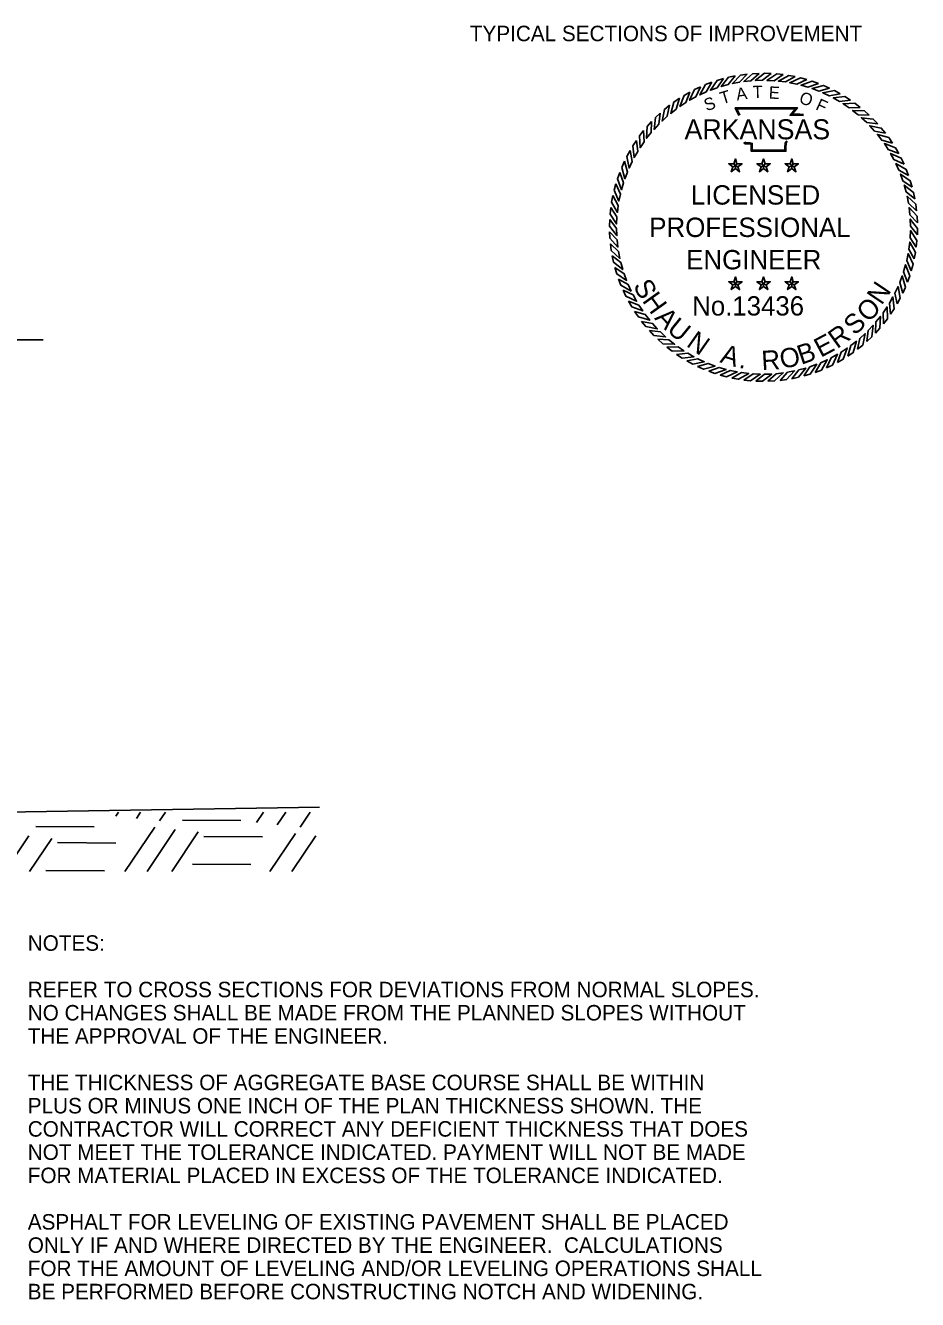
# Model space of a CAD drawing. Extents: x 1001270 to 1003428, y 1840152 to 1842912.
# Drawn here: x 1001393.92 to 1001428.48, y 1842430.26 to 1842479.61 of the extents above; entities that cross this region are included whole.
import ezdxf

# ---------------------------------------------------------------- set-up
doc = ezdxf.new("R2010")
doc.units = 0
for name, color, linetype in [('1', 7, 'Continuous'), ('19', 7, 'Continuous'), ('G-ANNO-SYMB', 7, 'Continuous')]:
    doc.layers.add(name, color=color, linetype=linetype)

msp = doc.modelspace()

# ---------------------------------------------------------------- linework, layer by layer
at = {"layer": '19'}
for p, q in [((1001374.315, 1842467.431), (1001394.601, 1842467.431)), ((1001393.111, 1842449.131), (1001405.316, 1842449.334)), ((1001397.423, 1842448.982), (1001397.529, 1842449.132)), ((1001398.217, 1842448.89), (1001398.383, 1842449.134)), ((1001399.113, 1842448.798), (1001399.339, 1842449.137)), ((1001402.877, 1842448.742), (1001403.139, 1842449.138)), ((1001403.672, 1842448.651), (1001404.003, 1842449.139)), ((1001404.567, 1842448.558), (1001404.948, 1842449.132)), ((1001394.326, 1842448.587), (1001396.586, 1842448.566)), ((1001397.775, 1842446.835), (1001398.927, 1842448.556)), ((1001400, 1842448.827), (1001402.261, 1842448.816)), ((1001393.12, 1842446.831), (1001394.046, 1842448.214)), ((1001394.075, 1842446.833), (1001394.942, 1842448.122)), ((1001398.629, 1842446.837), (1001399.722, 1842448.464)), ((1001399.585, 1842446.839), (1001400.617, 1842448.372)), ((1001400.83, 1842448.199), (1001403.101, 1842448.187)), ((1001403.385, 1842446.84), (1001404.381, 1842448.316)), ((1001404.24, 1842446.843), (1001405.176, 1842448.224)), ((1001395.166, 1842447.958), (1001397.426, 1842447.936)), ((1001400.389, 1842447.129), (1001402.648, 1842447.107)), ((1001394.713, 1842446.878), (1001396.984, 1842446.866))]:
    msp.add_line(p, q, dxfattribs=at)
at = {"layer": 'G-ANNO-SYMB'}
for points in [[(1001421.88, 1842477.723), (1001421.625, 1842477.69), (1001421.314, 1842477.356), (1001421.586, 1842477.408)], [(1001422.347, 1842477.755), (1001422.091, 1842477.742), (1001421.754, 1842477.433), (1001422.029, 1842477.464)], [(1001422.816, 1842477.75), (1001422.559, 1842477.757), (1001422.199, 1842477.476), (1001422.476, 1842477.485)], [(1001423.282, 1842477.708), (1001423.027, 1842477.736), (1001422.646, 1842477.483), (1001422.923, 1842477.47)], [(1001423.744, 1842477.63), (1001423.492, 1842477.677), (1001423.092, 1842477.456), (1001423.367, 1842477.421)], [(1001420.078, 1842477.236), (1001419.846, 1842477.126), (1001419.653, 1842476.711), (1001419.896, 1842476.845)], [(1001420.513, 1842477.41), (1001420.273, 1842477.319), (1001420.048, 1842476.921), (1001420.3, 1842477.035)], [(1001420.96, 1842477.55), (1001420.714, 1842477.478), (1001420.458, 1842477.099), (1001420.719, 1842477.193)], [(1001421.416, 1842477.655), (1001421.165, 1842477.602), (1001420.881, 1842477.244), (1001421.148, 1842477.317)], [(1001424.198, 1842477.516), (1001423.951, 1842477.583), (1001423.535, 1842477.393), (1001423.806, 1842477.337)], [(1001424.642, 1842477.366), (1001424.401, 1842477.452), (1001423.971, 1842477.296), (1001424.237, 1842477.219)], [(1001425.073, 1842477.182), (1001424.839, 1842477.287), (1001424.398, 1842477.165), (1001424.658, 1842477.067)], [(1001419.256, 1842476.787), (1001419.045, 1842476.642), (1001418.919, 1842476.203), (1001419.138, 1842476.373)], [(1001419.658, 1842477.028), (1001419.436, 1842476.9), (1001419.276, 1842476.471), (1001419.507, 1842476.624)], [(1001425.488, 1842476.965), (1001425.263, 1842477.088), (1001424.814, 1842477.001), (1001425.065, 1842476.883)], [(1001425.885, 1842476.716), (1001425.67, 1842476.856), (1001425.216, 1842476.805), (1001425.457, 1842476.667)], [(1001418.515, 1842476.215), (1001418.329, 1842476.039), (1001418.273, 1842475.585), (1001418.462, 1842475.787)], [(1001418.874, 1842476.516), (1001418.675, 1842476.355), (1001418.584, 1842475.907), (1001418.789, 1842476.093)], [(1001426.261, 1842476.437), (1001426.058, 1842476.594), (1001425.601, 1842476.578), (1001425.83, 1842476.422)], [(1001426.614, 1842476.129), (1001426.424, 1842476.301), (1001425.967, 1842476.321), (1001426.183, 1842476.148)], [(1001418.18, 1842475.888), (1001418.008, 1842475.697), (1001417.988, 1842475.241), (1001418.161, 1842475.457)], [(1001426.942, 1842475.794), (1001426.765, 1842475.981), (1001426.312, 1842476.036), (1001426.514, 1842475.847)], [(1001427.242, 1842475.435), (1001427.081, 1842475.634), (1001426.633, 1842475.726), (1001426.82, 1842475.521)], [(1001417.872, 1842475.535), (1001417.716, 1842475.332), (1001417.732, 1842474.875), (1001417.887, 1842475.104)], [(1001427.513, 1842475.053), (1001427.368, 1842475.265), (1001426.929, 1842475.391), (1001427.099, 1842475.172)], [(1001417.344, 1842474.762), (1001417.221, 1842474.537), (1001417.308, 1842474.088), (1001417.426, 1842474.339)], [(1001417.593, 1842475.159), (1001417.453, 1842474.944), (1001417.504, 1842474.49), (1001417.642, 1842474.73)], [(1001427.754, 1842474.651), (1001427.626, 1842474.873), (1001427.198, 1842475.033), (1001427.35, 1842474.802)], [(1001417.127, 1842474.347), (1001417.022, 1842474.113), (1001417.144, 1842473.672), (1001417.242, 1842473.931)], [(1001421.427, 1842474.167), (1001421.366, 1842474.251), (1001421.167, 1842474.251), (1001421.328, 1842474.135)], [(1001421.427, 1842474.167), (1001421.488, 1842474.251), (1001421.427, 1842474.44), (1001421.366, 1842474.251)], [(1001421.427, 1842474.167), (1001421.526, 1842474.135), (1001421.686, 1842474.251), (1001421.488, 1842474.251)], [(1001422.518, 1842474.167), (1001422.456, 1842474.251), (1001422.258, 1842474.251), (1001422.419, 1842474.135)], [(1001422.518, 1842474.167), (1001422.579, 1842474.251), (1001422.518, 1842474.44), (1001422.456, 1842474.251)], [(1001422.518, 1842474.167), (1001422.617, 1842474.135), (1001422.777, 1842474.251), (1001422.579, 1842474.251)], [(1001423.609, 1842474.167), (1001423.547, 1842474.251), (1001423.349, 1842474.251), (1001423.51, 1842474.135)], [(1001423.609, 1842474.167), (1001423.67, 1842474.251), (1001423.609, 1842474.44), (1001423.547, 1842474.251)], [(1001423.609, 1842474.167), (1001423.708, 1842474.135), (1001423.868, 1842474.251), (1001423.67, 1842474.251)], [(1001427.962, 1842474.231), (1001427.852, 1842474.463), (1001427.438, 1842474.656), (1001427.571, 1842474.413)], [(1001428.137, 1842473.796), (1001428.045, 1842474.036), (1001427.647, 1842474.261), (1001427.761, 1842474.009)], [(1001416.943, 1842473.916), (1001416.857, 1842473.674), (1001417.013, 1842473.245), (1001417.09, 1842473.511)], [(1001421.427, 1842474.167), (1001421.328, 1842474.135), (1001421.266, 1842473.946), (1001421.427, 1842474.063)], [(1001421.427, 1842474.167), (1001421.427, 1842474.063), (1001421.587, 1842473.946), (1001421.526, 1842474.135)], [(1001422.518, 1842474.167), (1001422.419, 1842474.135), (1001422.357, 1842473.946), (1001422.518, 1842474.063)], [(1001422.518, 1842474.167), (1001422.518, 1842474.063), (1001422.678, 1842473.946), (1001422.617, 1842474.135)], [(1001423.609, 1842474.167), (1001423.51, 1842474.135), (1001423.448, 1842473.946), (1001423.609, 1842474.063)], [(1001423.609, 1842474.167), (1001423.609, 1842474.063), (1001423.769, 1842473.946), (1001423.708, 1842474.135)], [(1001428.277, 1842473.349), (1001428.204, 1842473.596), (1001427.825, 1842473.851), (1001427.919, 1842473.591)], [(1001416.793, 1842473.472), (1001416.726, 1842473.224), (1001416.916, 1842472.808), (1001416.972, 1842473.08)], [(1001428.381, 1842472.893), (1001428.328, 1842473.144), (1001427.97, 1842473.428), (1001428.044, 1842473.161)], [(1001416.679, 1842473.018), (1001416.632, 1842472.766), (1001416.854, 1842472.366), (1001416.888, 1842472.641)], [(1001428.449, 1842472.429), (1001428.417, 1842472.684), (1001428.082, 1842472.996), (1001428.134, 1842472.723)], [(1001416.601, 1842472.556), (1001416.574, 1842472.301), (1001416.826, 1842471.92), (1001416.839, 1842472.196)], [(1001428.481, 1842471.962), (1001428.468, 1842472.218), (1001428.159, 1842472.555), (1001428.19, 1842472.28)], [(1001416.559, 1842472.089), (1001416.552, 1842471.833), (1001416.833, 1842471.473), (1001416.825, 1842471.75)], [(1001428.476, 1842471.494), (1001428.483, 1842471.75), (1001428.202, 1842472.11), (1001428.211, 1842471.833)], [(1001416.554, 1842471.621), (1001416.567, 1842471.365), (1001416.876, 1842471.028), (1001416.845, 1842471.303)], [(1001428.434, 1842471.027), (1001428.462, 1842471.282), (1001428.209, 1842471.663), (1001428.196, 1842471.387)], [(1001416.586, 1842471.154), (1001416.619, 1842470.899), (1001416.953, 1842470.587), (1001416.901, 1842470.86)], [(1001428.242, 1842470.111), (1001428.309, 1842470.358), (1001428.119, 1842470.775), (1001428.063, 1842470.503)], [(1001428.356, 1842470.565), (1001428.404, 1842470.817), (1001428.182, 1842471.217), (1001428.147, 1842470.942)], [(1001416.654, 1842470.69), (1001416.707, 1842470.439), (1001417.065, 1842470.154), (1001416.992, 1842470.422)], [(1001428.092, 1842469.667), (1001428.179, 1842469.909), (1001428.022, 1842470.338), (1001427.945, 1842470.072)], [(1001416.759, 1842470.234), (1001416.831, 1842469.987), (1001417.21, 1842469.732), (1001417.116, 1842469.992)], [(1001416.899, 1842469.786), (1001416.99, 1842469.547), (1001417.388, 1842469.322), (1001417.274, 1842469.574)], [(1001421.427, 1842469.599), (1001421.488, 1842469.683), (1001421.427, 1842469.872), (1001421.366, 1842469.683)], [(1001422.518, 1842469.599), (1001422.579, 1842469.683), (1001422.518, 1842469.872), (1001422.456, 1842469.683)], [(1001423.609, 1842469.599), (1001423.67, 1842469.683), (1001423.609, 1842469.872), (1001423.547, 1842469.683)], [(1001427.909, 1842469.236), (1001428.013, 1842469.47), (1001427.891, 1842469.911), (1001427.793, 1842469.651)], [(1001417.073, 1842469.352), (1001417.183, 1842469.12), (1001417.598, 1842468.927), (1001417.464, 1842469.17)], [(1001421.427, 1842469.599), (1001421.366, 1842469.683), (1001421.167, 1842469.683), (1001421.328, 1842469.567)], [(1001421.427, 1842469.599), (1001421.328, 1842469.567), (1001421.266, 1842469.378), (1001421.427, 1842469.495)], [(1001421.427, 1842469.599), (1001421.526, 1842469.567), (1001421.686, 1842469.683), (1001421.488, 1842469.683)], [(1001421.427, 1842469.599), (1001421.427, 1842469.495), (1001421.587, 1842469.378), (1001421.526, 1842469.567)], [(1001422.518, 1842469.599), (1001422.456, 1842469.683), (1001422.258, 1842469.683), (1001422.419, 1842469.567)], [(1001422.518, 1842469.599), (1001422.419, 1842469.567), (1001422.357, 1842469.378), (1001422.518, 1842469.495)], [(1001422.518, 1842469.599), (1001422.617, 1842469.567), (1001422.777, 1842469.683), (1001422.579, 1842469.683)], [(1001422.518, 1842469.599), (1001422.518, 1842469.495), (1001422.678, 1842469.378), (1001422.617, 1842469.567)], [(1001423.609, 1842469.599), (1001423.547, 1842469.683), (1001423.349, 1842469.683), (1001423.51, 1842469.567)], [(1001423.609, 1842469.599), (1001423.51, 1842469.567), (1001423.448, 1842469.378), (1001423.609, 1842469.495)], [(1001423.609, 1842469.599), (1001423.708, 1842469.567), (1001423.868, 1842469.683), (1001423.67, 1842469.683)], [(1001423.609, 1842469.599), (1001423.609, 1842469.495), (1001423.769, 1842469.378), (1001423.708, 1842469.567)], [(1001427.691, 1842468.821), (1001427.814, 1842469.046), (1001427.727, 1842469.495), (1001427.609, 1842469.244)], [(1001417.282, 1842468.932), (1001417.409, 1842468.71), (1001417.838, 1842468.55), (1001417.685, 1842468.781)], [(1001427.442, 1842468.424), (1001427.583, 1842468.639), (1001427.531, 1842469.093), (1001427.394, 1842468.853)], [(1001417.522, 1842468.53), (1001417.667, 1842468.318), (1001418.106, 1842468.192), (1001417.936, 1842468.411)], [(1001426.855, 1842467.695), (1001427.027, 1842467.885), (1001427.047, 1842468.342), (1001426.874, 1842468.126)], [(1001427.163, 1842468.048), (1001427.32, 1842468.251), (1001427.304, 1842468.708), (1001427.148, 1842468.479)], [(1001417.793, 1842468.148), (1001417.954, 1842467.949), (1001418.402, 1842467.857), (1001418.216, 1842468.062)], [(1001426.52, 1842467.368), (1001426.707, 1842467.544), (1001426.763, 1842467.998), (1001426.573, 1842467.795)], [(1001418.094, 1842467.789), (1001418.27, 1842467.602), (1001418.724, 1842467.547), (1001418.522, 1842467.736)], [(1001418.421, 1842467.454), (1001418.612, 1842467.282), (1001419.069, 1842467.262), (1001418.852, 1842467.435)], [(1001425.779, 1842466.796), (1001425.991, 1842466.941), (1001426.117, 1842467.38), (1001425.898, 1842467.21)], [(1001426.161, 1842467.067), (1001426.361, 1842467.228), (1001426.452, 1842467.676), (1001426.247, 1842467.49)], [(1001418.774, 1842467.146), (1001418.978, 1842466.989), (1001419.435, 1842467.005), (1001419.205, 1842467.161)], [(1001419.15, 1842466.867), (1001419.365, 1842466.726), (1001419.82, 1842466.778), (1001419.579, 1842466.915)], [(1001424.957, 1842466.347), (1001425.189, 1842466.457), (1001425.382, 1842466.872), (1001425.14, 1842466.738)], [(1001425.377, 1842466.555), (1001425.599, 1842466.683), (1001425.76, 1842467.111), (1001425.528, 1842466.959)], [(1001419.547, 1842466.618), (1001419.772, 1842466.495), (1001420.221, 1842466.582), (1001419.97, 1842466.7)], [(1001419.962, 1842466.401), (1001420.196, 1842466.296), (1001420.637, 1842466.418), (1001420.378, 1842466.516)], [(1001420.393, 1842466.217), (1001420.635, 1842466.13), (1001421.064, 1842466.287), (1001420.798, 1842466.364)], [(1001423.619, 1842465.928), (1001423.87, 1842465.981), (1001424.155, 1842466.339), (1001423.887, 1842466.265)], [(1001424.076, 1842466.033), (1001424.322, 1842466.105), (1001424.577, 1842466.484), (1001424.317, 1842466.39)], [(1001424.523, 1842466.173), (1001424.762, 1842466.264), (1001424.988, 1842466.662), (1001424.735, 1842466.548)], [(1001420.837, 1842466.067), (1001421.085, 1842466), (1001421.501, 1842466.19), (1001421.229, 1842466.246)], [(1001421.291, 1842465.953), (1001421.543, 1842465.906), (1001421.943, 1842466.127), (1001421.668, 1842466.162)], [(1001421.753, 1842465.875), (1001422.008, 1842465.847), (1001422.39, 1842466.1), (1001422.113, 1842466.113)], [(1001422.22, 1842465.833), (1001422.476, 1842465.826), (1001422.837, 1842466.107), (1001422.56, 1842466.098)], [(1001422.688, 1842465.828), (1001422.944, 1842465.841), (1001423.282, 1842466.15), (1001423.006, 1842466.119)], [(1001423.156, 1842465.86), (1001423.41, 1842465.893), (1001423.722, 1842466.227), (1001423.45, 1842466.175)]]:
    msp.add_lwpolyline(points, close=True, dxfattribs=at)
for points in [[(1001421.562, 1842476.121), (1001421.423, 1842476.423), (1001423.829, 1842476.424), (1001423.628, 1842476.171), (1001423.792, 1842476.174), (1001423.928, 1842476.175), (1001424.065, 1842476.16)], [(1001421.596, 1842476.137), (1001421.482, 1842476.385), (1001423.75, 1842476.386), (1001423.548, 1842476.132), (1001423.792, 1842476.135), (1001423.926, 1842476.137), (1001424.06, 1842476.123)], [(1001423.45, 1842475.113), (1001423.409, 1842475.08), (1001423.395, 1842475.03), (1001423.382, 1842474.905), (1001423.382, 1842474.739), (1001422.038, 1842474.739), (1001422.038, 1842474.963), (1001422.038, 1842475.013), (1001421.984, 1842475.03), (1001421.793, 1842475.03), (1001421.759, 1842475.082)], [(1001423.426, 1842475.143), (1001423.375, 1842475.101), (1001423.358, 1842475.037), (1001423.344, 1842474.907), (1001423.344, 1842474.777), (1001422.077, 1842474.777), (1001422.077, 1842474.963), (1001422.077, 1842475.041), (1001421.99, 1842475.068), (1001421.813, 1842475.068), (1001421.791, 1842475.102)]]:
    msp.add_lwpolyline(points, dxfattribs=at)

# ---------------------------------------------------------------- texts
at = {"layer": '1'}
msp.add_text('TYPICAL SECTIONS OF IMPROVEMENT', height=0.6, dxfattribs=at).set_placement((1001411.138, 1842479))
at = {"layer": '19'}
for s, p in [('NOTES:', (1001394.009, 1842443.768)), ('REFER TO CROSS SECTIONS FOR DEVIATIONS FROM NORMAL SLOPES.', (1001394.009, 1842441.968)), ('NO CHANGES SHALL BE MADE FROM THE PLANNED SLOPES WITHOUT', (1001394.009, 1842441.068)), ('THE APPROVAL OF THE ENGINEER.', (1001394.009, 1842440.168)), ('THE THICKNESS OF AGGREGATE BASE COURSE SHALL BE WITHIN', (1001394.009, 1842438.368)), ('PLUS OR MINUS ONE INCH OF THE PLAN THICKNESS SHOWN. THE', (1001394.009, 1842437.468)), ('CONTRACTOR WILL CORRECT ANY DEFICIENT THICKNESS THAT DOES', (1001394.009, 1842436.568)), ('NOT MEET THE TOLERANCE INDICATED. PAYMENT WILL NOT BE MADE', (1001394.009, 1842435.668)), ('FOR MATERIAL PLACED IN EXCESS OF THE TOLERANCE INDICATED.', (1001394.009, 1842434.768)), ('ASPHALT FOR LEVELING OF EXISTING PAVEMENT SHALL BE PLACED', (1001394.009, 1842432.968)), ('ONLY IF AND WHERE DIRECTED BY THE ENGINEER.  CALCULATIONS', (1001394.009, 1842432.068)), ('FOR THE AMOUNT OF LEVELING AND/OR LEVELING OPERATIONS SHALL', (1001394.009, 1842431.168)), ('BE PERFORMED BEFORE CONSTRUCTING NOTCH AND WIDENING.', (1001394.009, 1842430.268))]:
    msp.add_text(s, height=0.6, dxfattribs=at).set_placement(p)
at = {"layer": 'G-ANNO-SYMB'}
for s, height, rotation, p in [('A', 0.475, 8.6788, (1001421.489, 1842476.701)), ('T', 0.475, 1.4789, (1001422.102, 1842476.795)), ('E', 0.475, 356.672, (1001422.709, 1842476.781)), ('S', 0.475, 19.7726, (1001420.309, 1842476.279)), ('T', 0.475, 16.9015, (1001420.912, 1842476.55)), ('O', 0.475, 341.2218, (1001423.862, 1842476.618)), ('F', 0.475, 335.3628, (1001424.501, 1842476.368)), ('ARKANSAS', 0.7747, 360, (1001419.456, 1842475.2)), ('LICENSED', 0.75, 360, (1001419.696, 1842472.671)), ('PROFESSIONAL', 0.75, 360, (1001418.089, 1842471.416)), ('ENGINEER', 0.75, 360, (1001419.518, 1842470.162)), ('S', 0.75, 298.1636, (1001417.45, 1842469.532)), ('H', 0.75, 305.619, (1001417.792, 1842468.944)), ('N', 0.75, 56.1007, (1001427.092, 1842468.748)), ('No.13436', 0.747, 360, (1001419.754, 1842468.374)), ('O', 0.75, 44.7757, (1001426.571, 1842468.073)), ('A', 0.75, 313.4472, (1001418.268, 1842468.259)), ('U', 0.75, 320.9026, (1001418.735, 1842467.77)), ('S', 0.75, 43.4878, (1001426.055, 1842467.575)), ('R', 0.75, 35.6597, (1001425.366, 1842467.065)), ('N', 0.75, 324.9326, (1001419.491, 1842467.212)), ('B', 0.75, 18.885, (1001423.974, 1842466.462)), ('E', 0.75, 27.8315, (1001424.732, 1842466.733)), ('A', 0.75, 343.0991, (1001420.799, 1842466.568)), ('R', 0.75, 3.2287, (1001422.455, 1842466.255)), ('O', 0.75, 11.4296, (1001423.223, 1842466.303)), ('.', 0.75, 351.3, (1001421.536, 1842466.35))]:
    msp.add_text(s, height=height, rotation=rotation, dxfattribs=at).set_placement(p)

doc.saveas('drawing.dxf')
